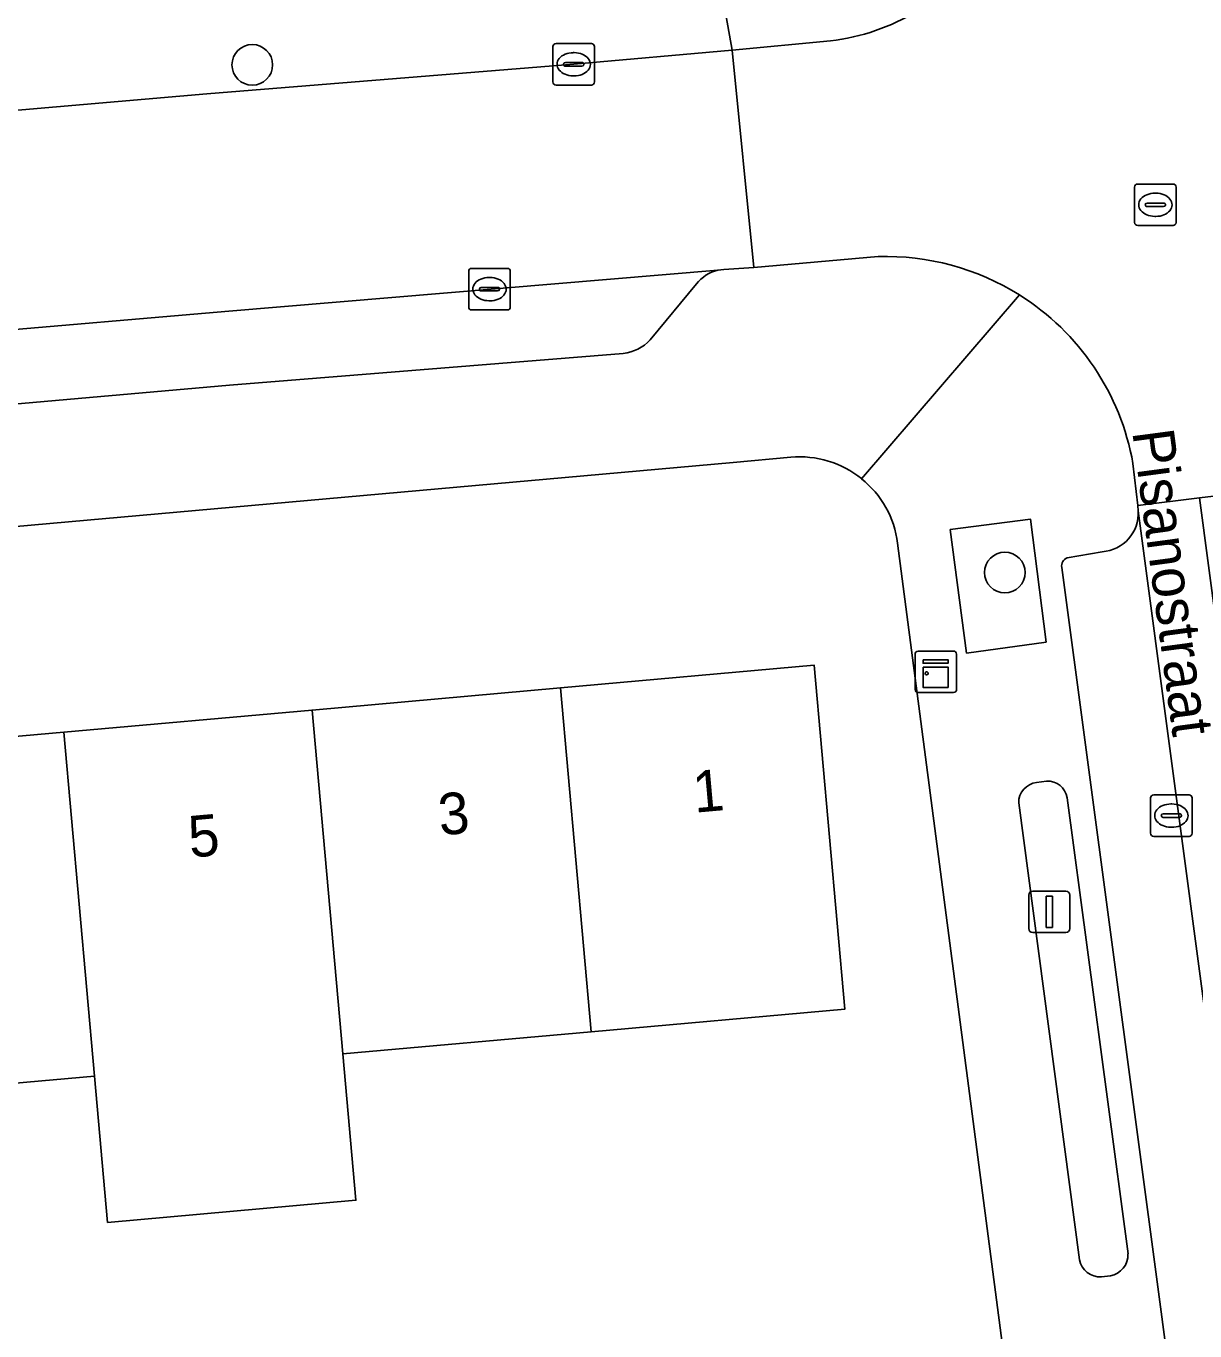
# Model space of a CAD drawing. Extents: x 160554 to 161248, y 385329 to 386506.
# Drawn here: x 161098.06 to 161126.19, y 385604.02 to 385635.43 of the extents above; entities that cross this region are included whole.
import ezdxf

# ---------------------------------------------------------------- set-up
doc = ezdxf.new("R2010")
doc.units = 0
for name, color, linetype in [('IMGEO_Boom', 7, 'Continuous'), ('IMGEO_Erf', 7, 'Continuous'), ('IMGEO_Groenvoorziening', 7, 'Continuous'), ('IMGEO_Kast', 7, 'Continuous'), ('IMGEO_Kolk', 7, 'Continuous'), ('IMGEO_Lichtmast', 7, 'Continuous'), ('IMGEO_Openbare_ruimte_label', 7, 'Continuous'), ('IMGEO_Pand', 7, 'Continuous'), ('IMGEO_Pand_nummerreeks', 7, 'Continuous'), ('IMGEO_Parkeervlak_open', 7, 'Continuous'), ('IMGEO_Rijbaan_lokaal_gesloten', 7, 'Continuous'), ('IMGEO_Rijbaan_lokaal_open', 7, 'Continuous'), ('IMGEO_Rioolput', 7, 'Continuous'), ('IMGEO_Voetpad_open', 7, 'Continuous')]:
    doc.layers.add(name, color=color, linetype=linetype)

msp = doc.modelspace()

# ---------------------------------------------------------------- linework, layer by layer
at = {"layer": 'IMGEO_Boom'}
for centre in [(161103.502, 385634.492), (161121.612, 385622.273)]:
    msp.add_circle(centre, 0.489, dxfattribs=at)
at = {"layer": 'IMGEO_Erf'}
for points in [[(161116.463, 385625.048), (161115.074, 385624.924), (161074.54, 385621.302)], [(161122.332, 385597.715), (161119.032, 385622.982)]]:
    msp.add_lwpolyline(points, dxfattribs=at)
msp.add_lwpolyline([(161093.728, 385609.619), (161087.752, 385609.085), (161081.776, 385608.551), (161082.077, 385605.183), (161075.957, 385604.636), (161075.661, 385608.005), (161075.611, 385608.572), (161074.933, 385616.289), (161081.037, 385616.833), (161087.013, 385617.366), (161092.989, 385617.899), (161098.966, 385618.431), (161104.942, 385618.964), (161110.918, 385619.497), (161117.024, 385620.041), (161117.763, 385611.765), (161111.657, 385611.22), (161105.681, 385610.686), (161105.995, 385607.167), (161100.019, 385606.633), (161099.705, 385610.152)], close=True, dxfattribs=at)
for centre, radius, start, end in [((161116.673, 385622.683), 2.375, 51.1474, 95.0834), ((161116.675, 385622.679), 2.376, 7.3205, 51.2334)]:
    msp.add_arc(centre, radius, start, end, dxfattribs=at)
at = {"layer": 'IMGEO_Groenvoorziening'}
msp.add_lwpolyline([(161120.692, 385620.332), (161122.605, 385620.601), (161122.231, 385623.555), (161120.299, 385623.308)], close=True, dxfattribs=at)
for points in [[(161122.616, 385617.251), (161122.375, 385617.22)], [(161121.945, 385616.729), (161123.408, 385605.729)], [(161124.576, 385605.873), (161123.109, 385616.854)], [(161123.936, 385605.321), (161124.151, 385605.346)]]:
    msp.add_lwpolyline(points, dxfattribs=at)
for centre, radius, start, end in [((161122.434, 385616.734), 0.489, 96.9545, 180.6241), ((161122.644, 385616.781), 0.471, 8.9381, 93.3748), ((161123.907, 385605.83), 0.509, 191.3943, 273.2172), ((161124.058, 385605.856), 0.518, 280.34, 1.891)]:
    msp.add_arc(centre, radius, start, end, dxfattribs=at)
at = {"layer": 'IMGEO_Kast'}
for p, q in [((161119.526, 385620.383), (161120.367, 385620.383)), ((161120.367, 385620.383), (161119.526, 385620.383)), ((161119.451, 385619.458), (161119.451, 385620.299)), ((161119.451, 385620.299), (161119.451, 385619.458)), ((161120.451, 385620.308), (161120.451, 385619.467)), ((161120.451, 385619.467), (161120.451, 385620.308)), ((161120.376, 385619.383), (161119.535, 385619.383)), ((161119.535, 385619.383), (161120.376, 385619.383))]:
    msp.add_line(p, q, dxfattribs=at)
for points in [[(161119.646, 385620.173), (161120.246, 385620.173), (161120.246, 385620.088), (161119.646, 385620.088), (161119.646, 385620.173)], [(161119.646, 385619.998), (161120.246, 385619.998), (161120.246, 385619.509), (161119.646, 385619.509), (161119.646, 385619.998)]]:
    msp.add_lwpolyline(points, dxfattribs=at)
msp.add_circle((161119.73, 385619.847), 0.0377, dxfattribs=at)
for centre, start, end in [((161119.529, 385620.305), 92.4484, 184.2845), ((161119.529, 385620.305), 92.4484, 184.2845), ((161120.373, 385620.305), 2.4484, 94.2845), ((161120.373, 385620.305), 2.4484, 94.2845), ((161119.529, 385619.461), 182.4484, 274.2845), ((161119.529, 385619.461), 182.4484, 274.2845), ((161120.373, 385619.461), 272.4484, 4.2845), ((161120.373, 385619.461), 272.4484, 4.2845)]:
    msp.add_arc(centre, 0.0779, start, end, dxfattribs=at)
at = {"layer": 'IMGEO_Kolk'}
for p, q in [((161110.736, 385634.08), (161110.736, 385634.932)), ((161110.811, 385635.006), (161111.663, 385635.006)), ((161111.737, 385634.932), (161111.737, 385634.08)), ((161110.995, 385634.5), (161110.995, 385634.512)), ((161111.038, 385634.549), (161111.436, 385634.549)), ((161111.224, 385634.786), (161111.249, 385634.786)), ((161111.479, 385634.512), (161111.479, 385634.5)), ((161111.433, 385634.463), (161111.035, 385634.463)), ((161111.247, 385634.226), (161111.222, 385634.226)), ((161111.663, 385634.006), (161110.811, 385634.006)), ((161108.71, 385628.668), (161108.71, 385629.52)), ((161108.785, 385629.594), (161109.637, 385629.594)), ((161109.711, 385629.52), (161109.711, 385628.668)), ((161109.198, 385629.374), (161109.223, 385629.374)), ((161108.969, 385629.088), (161108.969, 385629.1)), ((161109.407, 385629.051), (161109.009, 385629.051)), ((161109.012, 385629.137), (161109.41, 385629.137)), ((161109.453, 385629.1), (161109.453, 385629.088)), ((161109.637, 385628.594), (161108.785, 385628.594)), ((161109.221, 385628.814), (161109.196, 385628.814)), ((161125.194, 385616.923), (161126.046, 385616.923)), ((161125.119, 385615.997), (161125.119, 385616.849)), ((161125.607, 385616.703), (161125.632, 385616.703)), ((161126.12, 385616.849), (161126.12, 385615.997)), ((161125.378, 385616.417), (161125.378, 385616.429)), ((161125.816, 385616.38), (161125.418, 385616.38)), ((161125.421, 385616.466), (161125.819, 385616.466)), ((161125.862, 385616.429), (161125.862, 385616.417)), ((161125.63, 385616.143), (161125.605, 385616.143)), ((161126.046, 385615.923), (161125.194, 385615.923))]:
    msp.add_line(p, q, dxfattribs=at)
for points in [[(161110.736, 385634.08), (161110.736, 385634.932)], [(161110.811, 385635.006), (161111.663, 385635.006)], [(161111.737, 385634.932), (161111.737, 385634.08)], [(161111.663, 385634.006), (161110.811, 385634.006)], [(161108.71, 385628.668), (161108.71, 385629.52)], [(161108.785, 385629.594), (161109.637, 385629.594)], [(161109.711, 385629.52), (161109.711, 385628.668)], [(161109.637, 385628.594), (161108.785, 385628.594)], [(161125.194, 385616.923), (161126.046, 385616.923)], [(161125.119, 385615.997), (161125.119, 385616.849)], [(161126.12, 385616.849), (161126.12, 385615.997)], [(161126.046, 385615.923), (161125.194, 385615.923)]]:
    msp.add_lwpolyline(points, dxfattribs=at)
for centre, radius, start, end in [((161110.813, 385634.93), 0.0765, 91.552, 178.448), ((161110.813, 385634.93), 0.0765, 91.552, 178.448), ((161111.661, 385634.93), 0.0765, 1.552, 88.448), ((161111.661, 385634.93), 0.0765, 1.552, 88.448), ((161111.035, 385634.509), 0.0403, 85.8775, 175.7526), ((161111.032, 385634.499), 0.0366, 178.938, 274.7102), ((161111.436, 385634.506), 0.043, 264.8664, 352.4533), ((161111.44, 385634.511), 0.0386, 1.7309, 96.639), ((161110.813, 385634.082), 0.0765, 181.552, 268.448), ((161110.813, 385634.082), 0.0765, 181.552, 268.448), ((161111.661, 385634.082), 0.0765, 271.552, 358.448), ((161111.661, 385634.082), 0.0765, 271.552, 358.448), ((161108.787, 385629.518), 0.0765, 91.552, 178.448), ((161108.787, 385629.518), 0.0765, 91.552, 178.448), ((161109.635, 385629.518), 0.0765, 1.552, 88.448), ((161109.635, 385629.518), 0.0765, 1.552, 88.448), ((161109.009, 385629.097), 0.0403, 85.8775, 175.7526), ((161109.006, 385629.087), 0.0366, 178.938, 274.7102), ((161109.41, 385629.094), 0.043, 264.8664, 352.4533), ((161109.414, 385629.099), 0.0386, 1.7309, 96.639), ((161108.787, 385628.67), 0.0765, 181.552, 268.448), ((161108.787, 385628.67), 0.0765, 181.552, 268.448), ((161109.635, 385628.67), 0.0765, 271.552, 358.448), ((161109.635, 385628.67), 0.0765, 271.552, 358.448), ((161125.196, 385616.847), 0.0765, 91.552, 178.448), ((161125.196, 385616.847), 0.0765, 91.552, 178.448), ((161126.044, 385616.847), 0.0765, 1.552, 88.448), ((161126.044, 385616.847), 0.0765, 1.552, 88.448), ((161125.418, 385616.426), 0.0403, 85.8775, 175.7526), ((161125.415, 385616.416), 0.0366, 178.938, 274.7102), ((161125.819, 385616.423), 0.043, 264.8664, 352.4533), ((161125.823, 385616.428), 0.0386, 1.7309, 96.639), ((161125.196, 385615.999), 0.0765, 181.552, 268.448), ((161125.196, 385615.999), 0.0765, 181.552, 268.448), ((161126.044, 385615.999), 0.0765, 271.552, 358.448), ((161126.044, 385615.999), 0.0765, 271.552, 358.448)]:
    msp.add_arc(centre, radius, start, end, dxfattribs=at)
for centre, major_axis, ratio, start_param, end_param in [((161111.223, 385634.506), (-0.387, 0.002), 0.722429, 4.712389, 7.853982), ((161111.248, 385634.506), (-0.39, 0.002), 0.717154, 1.570796, 4.712389), ((161109.197, 385629.094), (-0.387, 0.002), 0.722429, 4.712389, 7.853982), ((161109.222, 385629.094), (-0.39, 0.002), 0.717154, 1.570796, 4.712389), ((161125.606, 385616.423), (-0.387, 0.002), 0.722429, 4.712389, 7.853982), ((161125.631, 385616.423), (-0.39, 0.002), 0.717154, 1.570796, 4.712389)]:
    msp.add_ellipse(centre, major_axis=major_axis, ratio=ratio, start_param=start_param, end_param=end_param, dxfattribs=at)
at = {"layer": 'IMGEO_Lichtmast'}
for p, q in [((161122.187, 385613.708), (161122.187, 385614.508)), ((161122.187, 385614.508), (161122.187, 385613.708)), ((161122.287, 385614.608), (161123.077, 385614.608)), ((161123.077, 385614.608), (161122.287, 385614.608)), ((161123.177, 385614.508), (161123.177, 385613.708)), ((161123.177, 385613.708), (161123.177, 385614.508)), ((161123.077, 385613.608), (161122.287, 385613.608)), ((161122.287, 385613.608), (161123.077, 385613.608))]:
    msp.add_line(p, q, dxfattribs=at)
msp.add_lwpolyline([(161122.607, 385614.483), (161122.757, 385614.483), (161122.757, 385613.733), (161122.607, 385613.733), (161122.607, 385614.483)], dxfattribs=at)
for centre, start, end in [((161122.287, 385614.508), 90, 180), ((161122.287, 385614.508), 90, 180), ((161123.077, 385614.508), 0, 90), ((161123.077, 385614.508), 360, 90), ((161122.287, 385613.708), 180, 270), ((161122.287, 385613.708), 180, 270), ((161123.077, 385613.708), 270, 0), ((161123.077, 385613.708), 270, 0)]:
    msp.add_arc(centre, 0.1, start, end, dxfattribs=at)
at = {"layer": 'IMGEO_Pand'}
for points in [[(161111.657, 385611.22), (161117.763, 385611.765), (161117.024, 385620.041), (161110.918, 385619.497)], [(161110.918, 385619.497), (161104.942, 385618.964), (161105.681, 385610.686), (161111.657, 385611.22)], [(161104.942, 385618.964), (161098.966, 385618.431), (161099.705, 385610.152), (161100.019, 385606.633), (161105.995, 385607.167), (161105.681, 385610.686)], [(161093.728, 385609.619), (161099.705, 385610.152), (161098.966, 385618.431), (161092.989, 385617.899)]]:
    msp.add_lwpolyline(points, close=True, dxfattribs=at)
at = {"layer": 'IMGEO_Parkeervlak_open'}
for points in [[(161114.704, 385629.548), (161102.937, 385628.566), (161078.255, 385626.442)], [(161113.08, 385627.872), (161114.194, 385629.219)], [(161081.278, 385624.873), (161102.952, 385626.783), (161112.431, 385627.546)], [(161127.335, 385604.916), (161124.823, 385623.758)], [(161123.954, 385622.773), (161123.112, 385622.627)], [(161122.98, 385622.395), (161125.357, 385604.603), (161129.312, 385574.75)]]:
    msp.add_lwpolyline(points, dxfattribs=at)
for centre, radius, start, end in [((161114.904, 385628.678), 0.893, 102.9568, 142.6952), ((161112.303, 385628.61), 1.071, 276.8542, 316.4875), ((161123.889, 385623.706), 0.936, 273.9981, 3.1623), ((161123.182, 385622.434), 0.205, 109.8277, 190.8956)]:
    msp.add_arc(centre, radius, start, end, dxfattribs=at)
at = {"layer": 'IMGEO_Rijbaan_lokaal_gesloten'}
msp.add_lwpolyline([(161129.001, 385603.744), (161126.296, 385624.071), (161124.809, 385623.89), (161124.823, 385623.758), (161127.335, 385604.916), (161131.436, 385573.892), (161131.444, 385573.829), (161131.983, 385569.741), (161132.394, 385566.679), (161136.719, 385534.065), (161137.405, 385528.949), (161137.609, 385527.41), (161138.381, 385521.493), (161138.515, 385520.471), (161140.193, 385507.547), (161141.009, 385501.397), (161143.236, 385484.558), (161144.696, 385484.751), (161142.364, 385502.586), (161138.335, 385533.123)], close=True, dxfattribs=at)
at = {"layer": 'IMGEO_Rijbaan_lokaal_open'}
for points in [[(161124.694, 385624.899), (161124.809, 385623.89), (161126.296, 385624.071), (161128.787, 385624.365), (161130.286, 385624.54), (161130.141, 385625.646), (161128.638, 385625.45), (161126.494, 385641.952)], [(161117.413, 385635.068), (161115.047, 385634.843), (161115.569, 385629.617), (161118.563, 385629.877)]]:
    msp.add_lwpolyline(points, dxfattribs=at)
msp.add_lwpolyline([(161115.047, 385634.843), (161111.237, 385634.506), (161102.409, 385633.794), (161095.811, 385633.223), (161075.852, 385631.439), (161076.316, 385626.277), (161078.255, 385626.442), (161102.937, 385628.566), (161114.704, 385629.548), (161114.846, 385629.57), (161115.569, 385629.617)], close=True, dxfattribs=at)
for centre, radius, start, end in [((161116.766, 385640.374), 5.345, 276.9536, 12.2089), ((161118.753, 385623.845), 6.035, 57.8747, 91.8035), ((161118.758, 385623.85), 6.028, 10.0214, 57.8916)]:
    msp.add_arc(centre, radius, start, end, dxfattribs=at)
at = {"layer": 'IMGEO_Rioolput'}
for p, q in [((161124.734, 385630.698), (161124.734, 385631.55)), ((161124.809, 385631.624), (161125.661, 385631.624)), ((161125.222, 385631.404), (161125.247, 385631.404)), ((161125.735, 385631.55), (161125.735, 385630.698)), ((161124.993, 385631.118), (161124.993, 385631.13)), ((161125.431, 385631.081), (161125.033, 385631.081)), ((161125.036, 385631.167), (161125.434, 385631.167)), ((161125.477, 385631.13), (161125.477, 385631.118)), ((161125.245, 385630.844), (161125.22, 385630.844)), ((161125.661, 385630.624), (161124.809, 385630.624))]:
    msp.add_line(p, q, dxfattribs=at)
for points in [[(161124.734, 385630.698), (161124.734, 385631.55)], [(161124.809, 385631.624), (161125.661, 385631.624)], [(161125.735, 385631.55), (161125.735, 385630.698)], [(161125.661, 385630.624), (161124.809, 385630.624)]]:
    msp.add_lwpolyline(points, dxfattribs=at)
for centre, radius, start, end in [((161124.811, 385631.548), 0.0765, 91.552, 178.448), ((161124.811, 385631.548), 0.0765, 91.552, 178.448), ((161125.659, 385631.548), 0.0765, 1.552, 88.448), ((161125.659, 385631.548), 0.0765, 1.552, 88.448), ((161125.033, 385631.127), 0.0403, 85.8775, 175.7526), ((161125.03, 385631.117), 0.0366, 178.938, 274.7102), ((161125.434, 385631.124), 0.043, 264.8664, 352.4533), ((161125.438, 385631.129), 0.0386, 1.7309, 96.639), ((161124.811, 385630.7), 0.0765, 181.552, 268.448), ((161124.811, 385630.7), 0.0765, 181.552, 268.448), ((161125.659, 385630.7), 0.0765, 271.552, 358.448), ((161125.659, 385630.7), 0.0765, 271.552, 358.448)]:
    msp.add_arc(centre, radius, start, end, dxfattribs=at)
for centre, major_axis, ratio, start_param, end_param in [((161125.221, 385631.124), (-0.387, 0.002), 0.722429, 4.712389, 7.853982), ((161125.246, 385631.124), (-0.39, 0.002), 0.717154, 1.570796, 4.712389)]:
    msp.add_ellipse(centre, major_axis=major_axis, ratio=ratio, start_param=start_param, end_param=end_param, dxfattribs=at)
at = {"layer": 'IMGEO_Voetpad_open'}
for points in [[(161091.644, 385839.67), (161090.577, 385836.855), (161089.36, 385832.82), (161089.359, 385832.428), (161093.052, 385804.928), (161093.658, 385800.418), (161096.873, 385775.58), (161099.829, 385752.532), (161099.92, 385751.819), (161100.53, 385747.059), (161103.849, 385721.182), (161103.528, 385716.968), (161104.544, 385708.871), (161105.47, 385701.933), (161107.028, 385690.183), (161107.754, 385684.63), (161108.994, 385675.141), (161109.438, 385671.741), (161109.961, 385671.806), (161111.073, 385663.16), (161112.38, 385652.994), (161113.833, 385641.697), (161115.047, 385634.843), (161117.413, 385635.068)], [(161118.563, 385629.877), (161115.569, 385629.617), (161114.846, 385629.57), (161114.704, 385629.548)], [(161114.194, 385629.219), (161113.08, 385627.872)], [(161118.163, 385624.532), (161121.962, 385628.956)], [(161121.962, 385628.956), (161118.163, 385624.532)], [(161112.431, 385627.546), (161102.952, 385626.783), (161081.278, 385624.873)], [(161074.54, 385621.302), (161115.074, 385624.924)], [(161115.074, 385624.924), (161116.463, 385625.048)], [(161124.823, 385623.758), (161124.809, 385623.89), (161124.694, 385624.899)], [(161119.032, 385622.982), (161122.332, 385597.715), (161122.515, 385596.316), (161125.326, 385574.791)], [(161123.112, 385622.627), (161123.954, 385622.773)], [(161129.312, 385574.75), (161125.357, 385604.603), (161122.98, 385622.395)], [(161122.375, 385617.22), (161122.616, 385617.251)], [(161123.408, 385605.729), (161121.945, 385616.729)], [(161123.109, 385616.854), (161124.576, 385605.873)], [(161124.151, 385605.346), (161123.936, 385605.321)]]:
    msp.add_lwpolyline(points, dxfattribs=at)
for points in [[(161113.833, 385641.697), (161113.554, 385638.574), (161109.428, 385637.533), (161055.034, 385632.68), (161055.294, 385629.619), (161056.224, 385629.703), (161075.852, 385631.439), (161095.811, 385633.223), (161102.409, 385633.794), (161111.237, 385634.506), (161115.047, 385634.843)], [(161120.692, 385620.332), (161120.299, 385623.308), (161122.231, 385623.555), (161122.605, 385620.601)]]:
    msp.add_lwpolyline(points, close=True, dxfattribs=at)
for centre, radius, start, end in [((161116.766, 385640.374), 5.345, 276.9536, 12.2089), ((161118.753, 385623.845), 6.035, 57.8747, 91.8035), ((161114.904, 385628.678), 0.893, 102.9568, 142.6952), ((161118.758, 385623.85), 6.028, 10.0214, 57.8916), ((161112.303, 385628.61), 1.071, 276.8542, 316.4875), ((161116.673, 385622.683), 2.375, 51.1474, 95.0834), ((161116.675, 385622.679), 2.376, 7.3205, 51.2334), ((161123.889, 385623.706), 0.936, 273.9981, 3.1623), ((161123.182, 385622.434), 0.205, 109.8277, 190.8956), ((161122.434, 385616.734), 0.489, 96.9545, 180.6241), ((161122.644, 385616.781), 0.471, 8.9381, 93.3748), ((161123.907, 385605.83), 0.509, 191.3943, 273.2172), ((161124.058, 385605.856), 0.518, 280.34, 1.891)]:
    msp.add_arc(centre, radius, start, end, dxfattribs=at)

# ---------------------------------------------------------------- texts
at = {"layer": 'IMGEO_Openbare_ruimte_label'}
msp.add_text('Pisanostraat', height=1, rotation=277.5871, dxfattribs=at).set_placement((161124.676, 385625.665))
at = {"layer": 'IMGEO_Pand_nummerreeks'}
for s, rotation, p in [('1', 5.0939, (161114.148, 385616.491)), ('3', 5.0939, (161108.021, 385615.945)), ('5', 5.0936, (161102.008, 385615.409))]:
    msp.add_text(s, height=1, rotation=rotation, dxfattribs=at).set_placement(p)

doc.saveas('drawing.dxf')
